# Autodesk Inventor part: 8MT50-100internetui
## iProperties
Created: 2010-10
Part Number: 8MT50-100internetui
Document SubType Name: Modeling
Designer: Darius
Author: Darius
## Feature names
1. Base1
